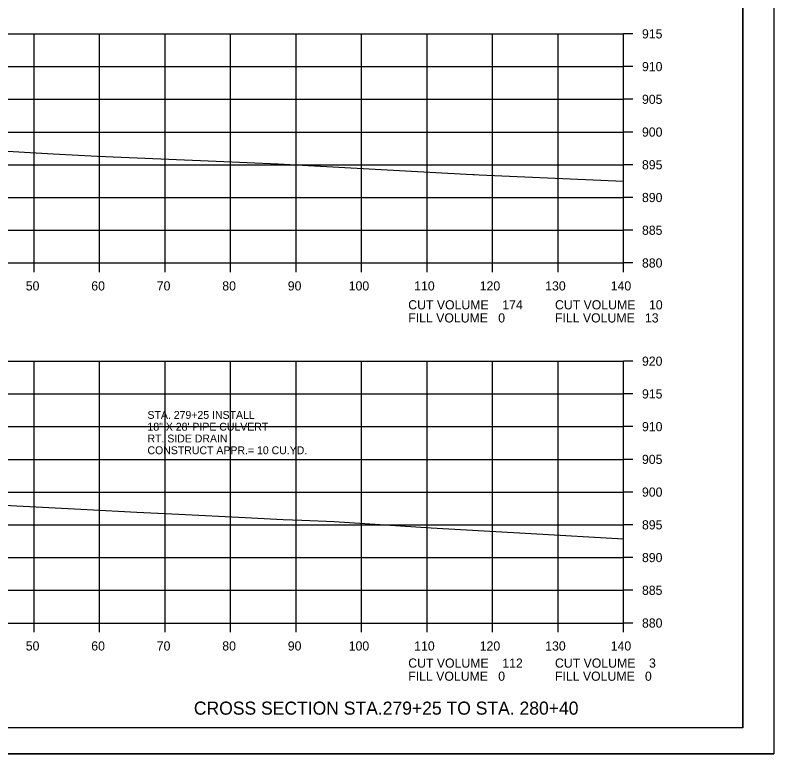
# Model space of a CAD drawing. Extents: x 1486524 to 1499135, y 326561 to 337924.
# Drawn here: x 1489030 to 1489145.8, y 331499.3 to 331612.1 of the extents above; entities that cross this region are included whole.
import ezdxf

# ---------------------------------------------------------------- set-up
doc = ezdxf.new("R2010")
doc.units = 0
for name, color, linetype in [('Default', 7, 'Continuous'), ('E_Const Align', 7, 'Continuous'), ('E_Const Align Station', 7, 'Continuous'), ('E_Ownership Information', 7, 'Continuous'), ('E_Property Line', 7, 'Continuous'), ('E_Proposed ROW Fig Annot', 7, 'Continuous'), ('E_Quarter Calls', 7, 'Continuous'), ('E_Tract Number', 7, 'Continuous')]:
    doc.layers.add(name, color=color, linetype=linetype)

msp = doc.modelspace()

# ---------------------------------------------------------------- linework, layer by layer
at = {"layer": 'E_Const Align'}
for p, q in [((1489122.89, 331574.26), (1489122.89, 331609.26)), ((1489124.29, 331609.26), (1489122.89, 331609.26)), ((1489124.29, 331604.26), (1489122.89, 331604.26)), ((1489124.29, 331599.26), (1489122.89, 331599.26)), ((1489124.29, 331594.26), (1489122.89, 331594.26)), ((1489124.29, 331589.26), (1489122.89, 331589.26)), ((1489124.29, 331584.26), (1489122.89, 331584.26)), ((1489124.29, 331579.26), (1489122.89, 331579.26)), ((1488842.89, 331574.26), (1489122.89, 331574.26)), ((1489032.89, 331572.86), (1489032.89, 331574.26)), ((1489042.89, 331572.86), (1489042.89, 331574.26)), ((1489052.89, 331572.86), (1489052.89, 331574.26)), ((1489062.89, 331572.86), (1489062.89, 331574.26)), ((1489072.89, 331572.86), (1489072.89, 331574.26)), ((1489082.89, 331572.86), (1489082.89, 331574.26)), ((1489092.89, 331572.86), (1489092.89, 331574.26)), ((1489102.89, 331572.86), (1489102.89, 331574.26)), ((1489112.89, 331572.86), (1489112.89, 331574.26)), ((1489122.89, 331572.86), (1489122.89, 331574.26)), ((1489124.29, 331574.26), (1489122.89, 331574.26)), ((1489122.89, 331519.26), (1489122.89, 331559.26)), ((1489124.29, 331559.26), (1489122.89, 331559.26)), ((1489124.29, 331554.26), (1489122.89, 331554.26)), ((1489124.29, 331549.26), (1489122.89, 331549.26)), ((1489124.29, 331544.26), (1489122.89, 331544.26)), ((1489124.29, 331539.26), (1489122.89, 331539.26)), ((1489124.29, 331534.26), (1489122.89, 331534.26)), ((1489124.29, 331529.26), (1489122.89, 331529.26)), ((1489124.29, 331524.26), (1489122.89, 331524.26)), ((1488842.89, 331519.26), (1489122.89, 331519.26)), ((1489032.89, 331517.86), (1489032.89, 331519.26)), ((1489042.89, 331517.86), (1489042.89, 331519.26)), ((1489052.89, 331517.86), (1489052.89, 331519.26)), ((1489062.89, 331517.86), (1489062.89, 331519.26)), ((1489072.89, 331517.86), (1489072.89, 331519.26)), ((1489082.89, 331517.86), (1489082.89, 331519.26)), ((1489092.89, 331517.86), (1489092.89, 331519.26)), ((1489102.89, 331517.86), (1489102.89, 331519.26)), ((1489112.89, 331517.86), (1489112.89, 331519.26)), ((1489122.89, 331517.86), (1489122.89, 331519.26)), ((1489124.29, 331519.26), (1489122.89, 331519.26))]:
    msp.add_line(p, q, dxfattribs=at)
at = {"layer": 'E_Ownership Information'}
for p, q in [((1488842.89, 331609.26), (1489122.89, 331609.26)), ((1489032.89, 331574.26), (1489032.89, 331609.26)), ((1489042.89, 331574.26), (1489042.89, 331609.26)), ((1489052.89, 331574.26), (1489052.89, 331609.26)), ((1489062.89, 331574.26), (1489062.89, 331609.26)), ((1489072.89, 331574.26), (1489072.89, 331609.26)), ((1489082.89, 331574.26), (1489082.89, 331609.26)), ((1489092.89, 331574.26), (1489092.89, 331609.26)), ((1489102.89, 331574.26), (1489102.89, 331609.26)), ((1489112.89, 331574.26), (1489112.89, 331609.26)), ((1489122.89, 331574.26), (1489122.89, 331609.26)), ((1488842.89, 331604.26), (1489122.89, 331604.26)), ((1488842.89, 331599.26), (1489122.89, 331599.26)), ((1488842.89, 331594.26), (1489122.89, 331594.26)), ((1488842.89, 331589.26), (1489122.89, 331589.26)), ((1488842.89, 331584.26), (1489122.89, 331584.26)), ((1488842.89, 331579.26), (1489122.89, 331579.26)), ((1488842.89, 331574.26), (1489122.89, 331574.26)), ((1488842.89, 331559.26), (1489122.89, 331559.26)), ((1489032.89, 331519.26), (1489032.89, 331559.26)), ((1489042.89, 331519.26), (1489042.89, 331559.26)), ((1489052.89, 331519.26), (1489052.89, 331559.26)), ((1489062.89, 331519.26), (1489062.89, 331559.26)), ((1489072.89, 331519.26), (1489072.89, 331559.26)), ((1489082.89, 331519.26), (1489082.89, 331559.26)), ((1489092.89, 331519.26), (1489092.89, 331559.26)), ((1489102.89, 331519.26), (1489102.89, 331559.26)), ((1489112.89, 331519.26), (1489112.89, 331559.26)), ((1489122.89, 331519.26), (1489122.89, 331559.26)), ((1488842.89, 331554.26), (1489122.89, 331554.26)), ((1488842.89, 331549.26), (1489122.89, 331549.26)), ((1488842.89, 331544.26), (1489122.89, 331544.26)), ((1488842.89, 331539.26), (1489122.89, 331539.26)), ((1488842.89, 331534.26), (1489122.89, 331534.26)), ((1488842.89, 331529.26), (1489122.89, 331529.26)), ((1488842.89, 331524.26), (1489122.89, 331524.26)), ((1488842.89, 331519.26), (1489122.89, 331519.26))]:
    msp.add_line(p, q, dxfattribs=at)
at = {"layer": 'E_Property Line'}
for q in [(1489141.07, 331708.72), (1488824.89, 331503.26)]:
    msp.add_line((1489141.07, 331503.26), q, dxfattribs=at)
at = {"layer": 'E_Quarter Calls'}
msp.add_line((1488812.48, 331499.28), (1489145.82, 331499.28), dxfattribs=at)
for points in [[(1488812.48, 331712.62), (1489145.82, 331712.62), (1489145.82, 331499.28), (1488812.48, 331499.28)], [(1489058.81, 331708.72), (1489058.81, 331698.84), (1489094.54, 331698.84), (1489094.54, 331695.92), (1489117.74, 331695.92), (1489117.74, 331671.59), (1489141.07, 331671.59), (1489141.07, 331503.26), (1488824.89, 331503.26), (1488824.89, 331708.72)]]:
    msp.add_lwpolyline(points, close=True, dxfattribs=at)
at = {"layer": 'E_Tract Number'}
for points in [[(1489018.32, 331591.94), (1489035.82, 331590.94), (1489042.59, 331590.56), (1489060.68, 331589.8), (1489070.14, 331589.39), (1489098.85, 331587.84), (1489099.87, 331587.79), (1489100.08, 331587.77), (1489100.84, 331587.73), (1489122.89, 331586.76)], [(1489028.31, 331537.24), (1489040.98, 331536.59), (1489048.57, 331536.21), (1489055, 331535.88), (1489065.09, 331535.36), (1489070.91, 331535.08), (1489073.74, 331534.99), (1489078.69, 331534.77), (1489093.53, 331533.81), (1489108.78, 331532.96), (1489122.89, 331532.13)]]:
    msp.add_lwpolyline(points, dxfattribs=at)

# ---------------------------------------------------------------- texts
at = {"layer": 'Default'}
for s, p in [('STA. 279+25 INSTALL', (1489050.2, 331550.45)), ('18" X 28\' PIPE CULVERT', (1489050.2, 331548.65)), ('RT. SIDE DRAIN', (1489050.2, 331546.85)), ('CONSTRUCT APPR.= 10 CU.YD.', (1489050.2, 331545.05))]:
    msp.add_text(s, height=1.2, dxfattribs=at).set_placement(p)
at = {"layer": 'E_Const Align Station'}
for s, p in [('915', (1489125.69, 331608.56)), ('910', (1489125.69, 331603.56)), ('905', (1489125.69, 331598.56)), ('900', (1489125.69, 331593.56)), ('895', (1489125.69, 331588.56)), ('890', (1489125.69, 331583.56)), ('885', (1489125.69, 331578.56)), ('880', (1489125.69, 331573.56)), ('50', (1489031.62, 331570.06)), ('60', (1489041.62, 331570.06)), ('70', (1489051.62, 331570.06)), ('80', (1489061.62, 331570.06)), ('90', (1489071.62, 331570.06)), ('100', (1489080.92, 331570.06)), ('110', (1489090.92, 331570.06)), ('120', (1489100.92, 331570.06)), ('130', (1489110.92, 331570.06)), ('140', (1489120.92, 331570.06)), ('CUT VOLUME    174', (1489090.01, 331567.17)), ('CUT VOLUME    10', (1489112.41, 331567.17)), ('FILL VOLUME   0', (1489090.01, 331565.17)), ('FILL VOLUME   13', (1489112.41, 331565.17)), ('920', (1489125.69, 331558.56)), ('915', (1489125.69, 331553.56)), ('910', (1489125.69, 331548.56)), ('905', (1489125.69, 331543.56)), ('900', (1489125.69, 331538.56)), ('895', (1489125.69, 331533.56)), ('890', (1489125.69, 331528.56)), ('885', (1489125.69, 331523.56)), ('880', (1489125.69, 331518.56)), ('50', (1489031.62, 331515.06)), ('60', (1489041.62, 331515.06)), ('70', (1489051.62, 331515.06)), ('80', (1489061.62, 331515.06)), ('90', (1489071.62, 331515.06)), ('100', (1489080.92, 331515.06)), ('110', (1489090.92, 331515.06)), ('120', (1489100.92, 331515.06)), ('130', (1489110.92, 331515.06)), ('140', (1489120.92, 331515.06)), ('CUT VOLUME    112', (1489090.01, 331512.44)), ('CUT VOLUME    3', (1489112.41, 331512.44)), ('FILL VOLUME   0', (1489090.01, 331510.44)), ('FILL VOLUME   0', (1489112.41, 331510.44))]:
    msp.add_text(s, height=1.4, dxfattribs=at).set_placement(p)
at = {"layer": 'E_Proposed ROW Fig Annot'}
msp.add_text('CROSS SECTION STA.279+25 TO STA. 280+40', height=2, dxfattribs=at).set_placement((1489057.28, 331505.26))

doc.saveas('drawing.dxf')
